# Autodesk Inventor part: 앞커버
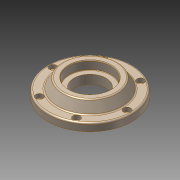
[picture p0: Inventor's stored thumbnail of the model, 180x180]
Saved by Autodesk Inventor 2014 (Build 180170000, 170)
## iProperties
Created: 2013-01
Part Number: 앞커버
Document SubType Name: Modeling
Designer: 한국산업디자인학원[gmhk.co.kr]
Density: 2.71 g/cm^3
Material: 알루미늄 6061
Mass: 415.969 g
Surface Area: 272.105 cm^2
Volume: 153.494 cm^3
Appearance: 알루미늄 - 평지(2)
Author: 한국산업디자인학원[gmhk.co.kr]
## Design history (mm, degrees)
sketch "스케치2"
  geometry: L1 (-55, 0)-(55, 0) reference; L2 (35.98, -6)-(-35.98, -6) reference; L3 (-42.5, -25)-(-42.5, 0) reference; L4 (-37, -6)-(-37, 0); L5 (-55, 0)-(-55, 10); L6 (-55, 10)-(-42.5, 10); L7 (-37, -6)-(-42.5, -6); L8 (-42.5, 10)-(-34.994, 23); L9 (-34.994, 23)-(0, 23); L10 (-55, 0)-(-42.5, 0); L11 (-42.5, -6)-(-42.5, 0); L12 (0, 0)-(0, 23); L13 (0, 0)-(-37, 0)
  constraints: 22 end point, 4 perpendicular, 3 collinear, 2 parallel, 2 point on line, 1 vertical, 2 other
  dimensions: "d2" = 10 distance of L1.start L5.end; "d4" = 120 deg angle of L8 L6; "d5" = 13 distance between parallel lines of L6 L9; "d6" = 74 diameter of L4 L12; "d7" = 85 diameter of L6.end L12
revolve "회전1" sketch "스케치2" stored, may be unused: angle "d8" = 90 deg
fillet "모깎기1" dims "d9" = 2
sketch "스케치3"
  geometry: C1 r 2.067 at (48.5, 0) reference; 1 further point
hole "구멍1" sketch "스케치3" at (48.5, 0) diameter "d10" = 5.5; stored, may be unused: countersink angle "d14" = 90 deg, drill point angle "d16" = 118 deg; dims "d11" = 6, "d12" = 9.5, "d13" = 5.4, "d15" = 8
fillet "모깎기2" dims "d20" = 3
chamfer "모따기1" distance "d21" = 1; stored, may be unused: second distance "d22" = 2, angle "d23" = 45 deg
sketch "스케치4"
  geometry: L1 (-33.84, 23)-(33.84, 23) reference; L2 (34, 0)-(-34, 0) reference; L3 (0, 0)-(0, 23); L4 (27.5, 21.9)-(27.5, 12.1); L5 (27, 11.6)-(21, 11.6); L6 (21, 11.6)-(21, 0); L7 (27.5, 21.9)-(28.135, 23); A1 r 0.5 centre (27, 12.1) between (27, 11.6) and (27.5, 12.1)
  constraints: 10 end point, 2 perpendicular, 2 point on circle, 2 point on line, 2 tangent, 1 centre point, 1 midpoint, 1 parallel
  dimensions: "d24" = 11.4 distance between parallel lines of L5 L1; "d25" = 1.1 distance from line of L4.start L1; "d26" = 30 deg angle of L7 L4; "d27" = 0.5 radius of A1; "d28" = 55 diameter of L4 L3; "d29" = 42 diameter of L6 L3
revolve "회전2" sketch "스케치4" stored, may be unused: angle "d30" = 90 deg
node "솔리드1"
pattern_circular "원형 패턴1" dims angle "d18" = 360 deg
node "참조1"
node "참조2"
node "참조3"
